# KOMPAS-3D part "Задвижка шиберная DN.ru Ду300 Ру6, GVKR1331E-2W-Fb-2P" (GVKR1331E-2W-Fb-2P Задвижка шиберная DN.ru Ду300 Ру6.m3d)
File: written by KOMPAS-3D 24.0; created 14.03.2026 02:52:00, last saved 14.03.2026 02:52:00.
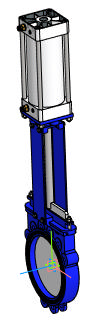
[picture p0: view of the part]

Document properties: Автор: DN.RU; Полное имя файла: D:\PROJECT CAD\DN.RU\...192.(ACTUALE) GVKR1331E-2W-Fb-2P Задвижка шиберная DN.ru Ру6-10\DN300_PN6\GVKR1331E-2W-Fb-2P Задвижка шиберная DN.ru Ду300 Ру6.m3d

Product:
- Body: Твердое тело1  | qty 1
    Масса: 165.094964
- Part/product: Задвижка шиберная DN.ru Ду300 Ру6  | designation GVKR1331E-2W-Fb-2P
    Масса: 74
    Раздел спецификации: Прочие изделия
    Комментарий: D040-10118
    Примечание: D040-10118
    additional columns: Чугун, серый

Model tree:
1. Твердое тело1  (labels: Твердое тело1)

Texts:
  GVKR1331E-2W-Fb-2P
